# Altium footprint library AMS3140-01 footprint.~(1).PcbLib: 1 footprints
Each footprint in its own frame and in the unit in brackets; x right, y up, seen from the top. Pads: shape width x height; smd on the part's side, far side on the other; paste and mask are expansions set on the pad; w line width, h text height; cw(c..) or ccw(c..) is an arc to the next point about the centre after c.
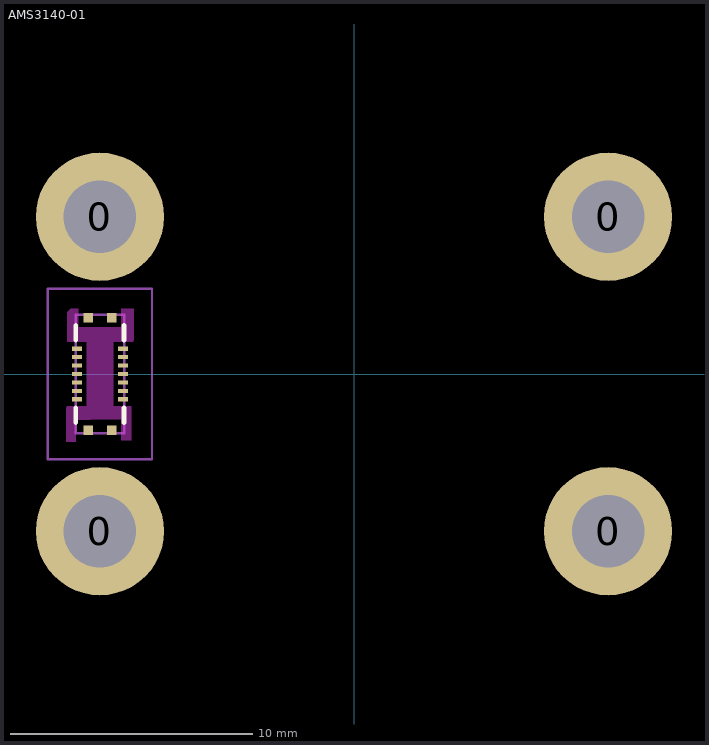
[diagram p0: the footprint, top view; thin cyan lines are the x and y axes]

## AMS3140-01 [mm]
pads (22):
  round 5.3 / inner round 3.6 / far side round 5.3 hole 3: 0(-10.5,-6.5) 0(-10.5,6.5) 0(10.5,-6.5) 0(10.5,6.5)
  rect 0.4x0.18 smd: 1(-9.55,-1.05) 2(-11.45,-1.05) 3(-9.55,-0.7) 4(-11.45,-0.7) 5(-9.55,-0.35) 6(-11.45,-0.35) 7(-9.55,0) 8(-11.45,0) 9(-9.55,0.35) 10(-11.45,0.35) 11(-9.55,0.7) 12(-11.45,0.7) 13(-9.55,1.05) 14(-11.45,1.05)
  rect 0.385x0.4 smd: MP1(-10.017,-2.33) MP2(-10.983,-2.33) MP3(-10.017,2.33) MP4(-10.983,2.33)
Top Overlay:
  lines w0.2: -11.5,-2 -11.5,-1.4 ; -11.5,1.4 -11.5,2 ; -9.5,-2 -9.5,-1.4 ; -9.5,1.4 -9.5,2
Top Paste:
  circle w1: c-10.5,6.5 r2.05
  circle w1: c-10.5,-6.5 r2.05
  circle w1: c10.5,6.5 r2.05
  circle w1: c10.5,-6.5 r2.05
Keep-Out Layer:
  region: -11,-1.9 -11.5,-1.9 -11.5,-2.769 -11.477,-2.792 -11.9,-2.8 -11.9,-1.397 -11.843,-1.34 -11.05,-1.34 -11.05,1.34 -11.843,1.34 -11.844,2.556 -11.7,2.7 -11.4,2.7 -11.4,1.955 -11.375,1.93 -9.625,1.93 -9.624,2.7 -9.1,2.7 -9.1,1.388 -9.148,1.34 -9.95,1.34 -9.95,-1.34 -9.197,-1.34 -9.197,-2.097 -9.203,-2.73 -9.624,-2.73 -9.625,-1.9 -10.9,-1.9
Mechanical 13:
  circle w0.102: c-10.5,6.5 r1.5
  circle w0.102: c-10.5,-6.5 r1.5
  circle w0.102: c10.5,6.5 r1.5
  circle w0.102: c10.5,-6.5 r1.5
  lines w0.1: -11.5,-2.45 -11.5,2.45 -9.5,2.45 -9.5,-2.45 -11.5,-2.45
Mechanical 15:
  lines w0.1: -12.65,-3.53 -12.65,3.53 -8.35,3.53 -8.35,-3.53 -12.65,-3.53
3D body "247-682(TMDs).step": height 9.44, standoff 0.1, extent -15,-9.5 15,9.5
3D body "9774010943 (rev1).stp": height 1.01, standoff -1.39, extent -12.675,4.328 -8.325,8.672
3D body "9774010943 (rev1).stp": height 1.01, standoff -1.39, extent -12.675,-8.672 -8.325,-4.328
3D body "9774010943 (rev1).stp": height 1.01, standoff -1.39, extent 8.325,4.328 12.675,8.672
3D body "9774010943 (rev1).stp": height 1.01, standoff -1.39, extent 8.325,-8.672 12.675,-4.328
3D body "101R014FB110.stp": height 0.78, standoff 0, extent -11.505,-2.45 -9.505,2.45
